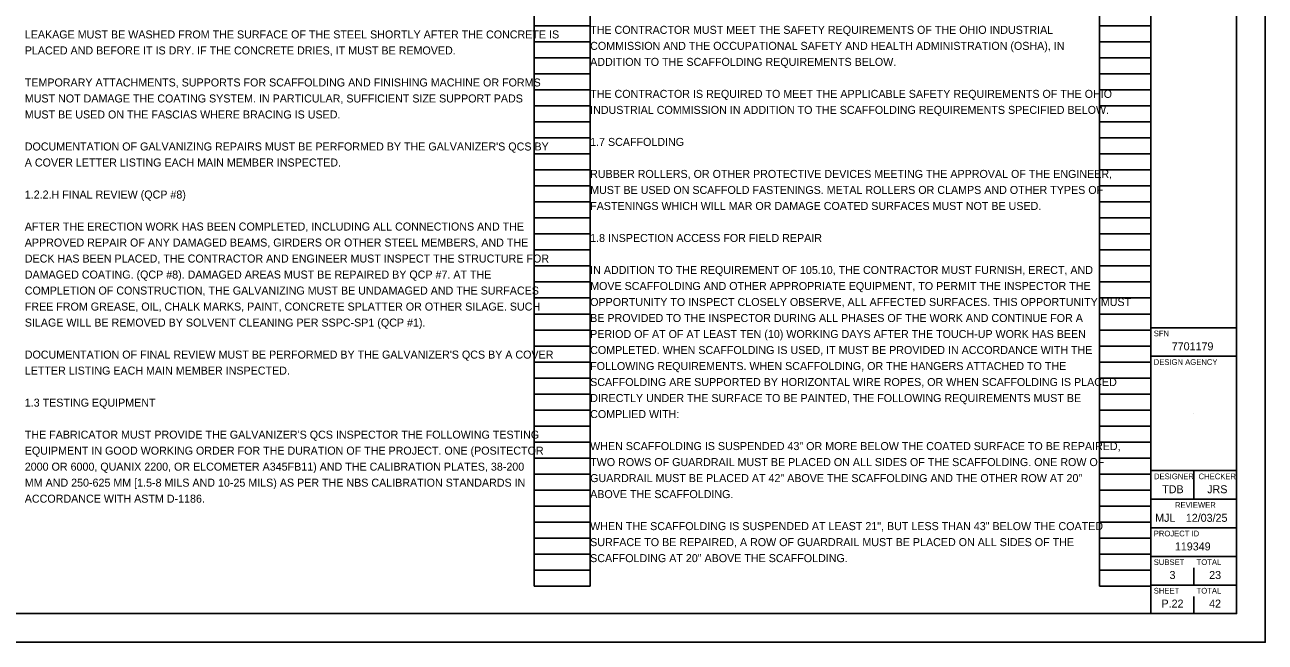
# Model space of a CAD drawing. Extents: x 0 to 34, y 0 to 22.
# Drawn here: x 12.29 to 34, y 0 to 10.8 of the extents above; entities that cross this region are included whole.
import ezdxf

# ---------------------------------------------------------------- set-up
doc = ezdxf.new("R2010")
doc.units = 0
for name, color, linetype in [('SH_Border', 7, 'Continuous'), ('SH_Cut_Line', 7, 'Continuous'), ('SH_Data', 7, 'Continuous'), ('SH_Text', 7, 'Continuous')]:
    doc.layers.add(name, color=color, linetype=linetype)

msp = doc.modelspace()

# ---------------------------------------------------------------- linework, layer by layer
at = {"layer": 'SH_Border'}
for p, q in [((32, 0.5), (32, 21.5)), ((32, 5.5), (33.5, 5.5)), ((32, 5), (33.5, 5)), ((32, 3), (33.5, 3)), ((32.75, 3), (32.75, 2.5)), ((32, 2.5), (33.5, 2.5)), ((32, 2), (33.5, 2)), ((32, 1.5), (33.5, 1.5)), ((32, 1), (33.5, 1))]:
    msp.add_line(p, q, dxfattribs=at)
msp.add_lwpolyline([(1.5, 21.5), (33.5, 21.5), (33.5, 0.5), (1.5, 0.5)], close=True, dxfattribs=at)
at = {"layer": 'SH_Cut_Line'}
msp.add_lwpolyline([(0, 0), (34, 0), (34, 22), (0, 22)], close=True, dxfattribs=at)
at = {"layer": 'SH_Data'}
for p, q in [((21.207, 0.98), (21.207, 21.14)), ((22.187, 0.98), (22.187, 21.14)), ((31.1, 0.98), (31.1, 21.14)), ((32, 0.98), (32, 21.14)), ((21.207, 10.78), (22.187, 10.78)), ((31.1, 10.78), (32, 10.78)), ((21.207, 10.5), (22.187, 10.5)), ((31.1, 10.5), (32, 10.5)), ((21.207, 10.22), (22.187, 10.22)), ((31.1, 10.22), (32, 10.22)), ((21.207, 9.94), (22.187, 9.94)), ((31.1, 9.94), (32, 9.94)), ((21.207, 9.66), (22.187, 9.66)), ((31.1, 9.66), (32, 9.66)), ((21.207, 9.38), (22.187, 9.38)), ((31.1, 9.38), (32, 9.38)), ((21.207, 9.1), (22.187, 9.1)), ((31.1, 9.1), (32, 9.1)), ((21.207, 8.82), (22.187, 8.82)), ((31.1, 8.82), (32, 8.82)), ((21.207, 8.54), (22.187, 8.54)), ((31.1, 8.54), (32, 8.54)), ((21.207, 8.26), (22.187, 8.26)), ((31.1, 8.26), (32, 8.26)), ((21.207, 7.98), (22.187, 7.98)), ((31.1, 7.98), (32, 7.98)), ((21.207, 7.7), (22.187, 7.7)), ((31.1, 7.7), (32, 7.7)), ((21.207, 7.42), (22.187, 7.42)), ((31.1, 7.42), (32, 7.42)), ((21.207, 7.14), (22.187, 7.14)), ((31.1, 7.14), (32, 7.14)), ((21.207, 6.86), (22.187, 6.86)), ((31.1, 6.86), (32, 6.86)), ((21.207, 6.58), (22.187, 6.58)), ((31.1, 6.58), (32, 6.58)), ((21.207, 6.3), (22.187, 6.3)), ((31.1, 6.3), (32, 6.3)), ((21.207, 6.02), (22.187, 6.02)), ((31.1, 6.02), (32, 6.02)), ((21.207, 5.74), (22.187, 5.74)), ((31.1, 5.74), (32, 5.74)), ((21.207, 5.46), (22.187, 5.46)), ((31.1, 5.46), (32, 5.46)), ((21.207, 5.18), (22.187, 5.18)), ((31.1, 5.18), (32, 5.18)), ((21.207, 4.9), (22.187, 4.9)), ((31.1, 4.9), (32, 4.9)), ((21.207, 4.62), (22.187, 4.62)), ((31.1, 4.62), (32, 4.62)), ((21.207, 4.34), (22.187, 4.34)), ((31.1, 4.34), (32, 4.34)), ((21.207, 4.06), (22.187, 4.06)), ((31.1, 4.06), (32, 4.06)), ((32.75, 4), (32.75, 4)), ((21.207, 3.78), (22.187, 3.78)), ((31.1, 3.78), (32, 3.78)), ((21.207, 3.5), (22.187, 3.5)), ((31.1, 3.5), (32, 3.5)), ((21.207, 3.22), (22.187, 3.22)), ((31.1, 3.22), (32, 3.22)), ((21.207, 2.94), (22.187, 2.94)), ((31.1, 2.94), (32, 2.94)), ((21.207, 2.66), (22.187, 2.66)), ((31.1, 2.66), (32, 2.66)), ((21.207, 2.38), (22.187, 2.38)), ((31.1, 2.38), (32, 2.38)), ((21.207, 2.1), (22.187, 2.1)), ((31.1, 2.1), (32, 2.1)), ((21.207, 1.82), (22.187, 1.82)), ((31.1, 1.82), (32, 1.82)), ((21.207, 1.54), (22.187, 1.54)), ((31.1, 1.54), (32, 1.54)), ((21.207, 1.26), (22.187, 1.26)), ((31.1, 1.26), (32, 1.26)), ((32.75, 1), (32.75, 1.3)), ((21.207, 0.98), (22.187, 0.98)), ((31.1, 0.98), (32, 0.98)), ((32.375, 0.675), (32.375, 0.675)), ((32.75, 0.5), (32.75, 0.8))]:
    msp.add_line(p, q, dxfattribs=at)

# ---------------------------------------------------------------- texts
for s, height, p in [('SFN', 0.1, (32.05, 5.35)), ('7701179', 0.14, (32.365, 5.105)), ('DESIGN AGENCY', 0.1, (32.05, 4.85)), ('DESIGNER', 0.1, (32.054, 2.85)), ('CHECKER', 0.1, (32.835, 2.85)), ('TDB', 0.14, (32.198, 2.605)), ('JRS', 0.14, (32.985, 2.605)), ('REVIEWER', 0.1, (32.422, 2.35)), ('MJL', 0.14, (32.075, 2.105)), ('12/03/25', 0.14, (32.611, 2.105)), ('PROJECT ID', 0.1, (32.05, 1.85)), ('119349', 0.14, (32.42, 1.605)), ('SUBSET', 0.1, (32.05, 1.35)), ('TOTAL', 0.1, (32.8, 1.35)), ('3', 0.14, (32.326, 1.105)), ('23', 0.14, (33.02, 1.105)), ('SHEET', 0.1, (32.05, 0.85)), ('TOTAL', 0.1, (32.8, 0.85)), ('P.22', 0.14, (32.185, 0.605)), ('42', 0.14, (33.019, 0.605))]:
    msp.add_text(s, height=height, dxfattribs=at).set_placement(p)
at = {"layer": 'SH_Text'}
for s, p in [('LEAKAGE MUST BE WASHED FROM THE SURFACE OF THE STEEL SHORTLY AFTER THE CONCRETE IS ', (12.293, 10.56)), ('THE CONTRACTOR MUST MEET THE SAFETY REQUIREMENTS OF THE OHIO INDUSTRIAL ', (22.187, 10.64)), ('PLACED AND BEFORE IT IS DRY. IF THE CONCRETE DRIES, IT MUST BE REMOVED.', (12.293, 10.28)), ('COMMISSION AND THE OCCUPATIONAL SAFETY AND HEALTH ADMINISTRATION (OSHA), IN ', (22.187, 10.36)), ('ADDITION TO THE SCAFFOLDING REQUIREMENTS BELOW.', (22.187, 10.08)), ('TEMPORARY ATTACHMENTS, SUPPORTS FOR SCAFFOLDING AND FINISHING MACHINE OR FORMS ', (12.293, 9.72)), ('MUST NOT DAMAGE THE COATING SYSTEM. IN PARTICULAR, SUFFICIENT SIZE SUPPORT PADS ', (12.293, 9.44)), ('THE CONTRACTOR IS REQUIRED TO MEET THE APPLICABLE SAFETY REQUIREMENTS OF THE OHIO ', (22.187, 9.52)), ('INDUSTRIAL COMMISSION IN ADDITION TO THE SCAFFOLDING REQUIREMENTS SPECIFIED BELOW.', (22.187, 9.24)), ('MUST BE USED ON THE FASCIAS WHERE BRACING IS USED.', (12.293, 9.16)), ("DOCUMENTATION OF GALVANIZING REPAIRS MUST BE PERFORMED BY THE GALVANIZER'S QCS BY ", (12.293, 8.6)), ('1.7 SCAFFOLDING', (22.187, 8.68)), ('A COVER LETTER LISTING EACH MAIN MEMBER INSPECTED.', (12.293, 8.32)), ('RUBBER ROLLERS, OR OTHER PROTECTIVE DEVICES MEETING THE APPROVAL OF THE ENGINEER, ', (22.187, 8.12)), ('1.2.2.H FINAL REVIEW (QCP #8)', (12.293, 7.76)), ('MUST BE USED ON SCAFFOLD FASTENINGS. METAL ROLLERS OR CLAMPS AND OTHER TYPES OF ', (22.187, 7.84)), ('FASTENINGS WHICH WILL MAR OR DAMAGE COATED SURFACES MUST NOT BE USED.', (22.187, 7.56)), ('AFTER THE ERECTION WORK HAS BEEN COMPLETED, INCLUDING ALL CONNECTIONS AND THE ', (12.293, 7.2)), ('APPROVED REPAIR OF ANY DAMAGED BEAMS, GIRDERS OR OTHER STEEL MEMBERS, AND THE ', (12.293, 6.92)), ('1.8 INSPECTION ACCESS FOR FIELD REPAIR', (22.187, 7)), ('DECK HAS BEEN PLACED, THE CONTRACTOR AND ENGINEER MUST INSPECT THE STRUCTURE FOR ', (12.293, 6.64)), ('IN ADDITION TO THE REQUIREMENT OF 105.10, THE CONTRACTOR MUST FURNISH, ERECT, AND ', (22.187, 6.44)), ('DAMAGED COATING. (QCP #8). DAMAGED AREAS MUST BE REPAIRED BY QCP #7. AT THE ', (12.293, 6.36)), ('MOVE SCAFFOLDING AND OTHER APPROPRIATE EQUIPMENT, TO PERMIT THE INSPECTOR THE ', (22.187, 6.16)), ('COMPLETION OF CONSTRUCTION, THE GALVANIZING MUST BE UNDAMAGED AND THE SURFACES ', (12.293, 6.08)), ('FREE FROM GREASE, OIL, CHALK MARKS, PAINT, CONCRETE SPLATTER OR OTHER SILAGE. SUCH ', (12.293, 5.8)), ('OPPORTUNITY TO INSPECT CLOSELY OBSERVE, ALL AFFECTED SURFACES. THIS OPPORTUNITY MUST ', (22.187, 5.88)), ('SILAGE WILL BE REMOVED BY SOLVENT CLEANING PER SSPC-SP1 (QCP #1).', (12.293, 5.52)), ('BE PROVIDED TO THE INSPECTOR DURING ALL PHASES OF THE WORK AND CONTINUE FOR A ', (22.187, 5.6)), ('PERIOD OF AT OF AT LEAST TEN (10) WORKING DAYS AFTER THE TOUCH-UP WORK HAS BEEN ', (22.187, 5.32)), ("DOCUMENTATION OF FINAL REVIEW MUST BE PERFORMED BY THE GALVANIZER'S QCS BY A COVER ", (12.293, 4.96)), ('COMPLETED. WHEN SCAFFOLDING IS USED, IT MUST BE PROVIDED IN ACCORDANCE WITH THE ', (22.187, 5.04)), ('LETTER LISTING EACH MAIN MEMBER INSPECTED.', (12.293, 4.68)), ('FOLLOWING REQUIREMENTS. WHEN SCAFFOLDING, OR THE HANGERS ATTACHED TO THE ', (22.187, 4.76)), ('SCAFFOLDING ARE SUPPORTED BY HORIZONTAL WIRE ROPES, OR WHEN SCAFFOLDING IS PLACED ', (22.187, 4.48)), ('DIRECTLY UNDER THE SURFACE TO BE PAINTED, THE FOLLOWING REQUIREMENTS MUST BE ', (22.187, 4.2)), ('1.3 TESTING EQUIPMENT', (12.293, 4.12)), ('COMPLIED WITH:', (22.187, 3.92)), ("THE FABRICATOR MUST PROVIDE THE GALVANIZER'S QCS INSPECTOR THE FOLLOWING TESTING ", (12.293, 3.56)), ('WHEN SCAFFOLDING IS SUSPENDED 43" OR MORE BELOW THE COATED SURFACE TO BE REPAIRED, ', (22.187, 3.36)), ('EQUIPMENT IN GOOD WORKING ORDER FOR THE DURATION OF THE PROJECT. ONE (POSITECTOR ', (12.293, 3.28)), ('2000 OR 6000, QUANIX 2200, OR ELCOMETER A345FB11) AND THE CALIBRATION PLATES, 38-200 ', (12.293, 3)), ('TWO ROWS OF GUARDRAIL MUST BE PLACED ON ALL SIDES OF THE SCAFFOLDING. ONE ROW OF ', (22.187, 3.08)), ('MM AND 250-625 MM [1.5-8 MILS AND 10-25 MILS) AS PER THE NBS CALIBRATION STANDARDS IN ', (12.293, 2.72)), ('GUARDRAIL MUST BE PLACED AT 42" ABOVE THE SCAFFOLDING AND THE OTHER ROW AT 20" ', (22.187, 2.8)), ('ABOVE THE SCAFFOLDING.', (22.187, 2.52)), ('ACCORDANCE WITH ASTM D-1186.', (12.293, 2.44)), ('WHEN THE SCAFFOLDING IS SUSPENDED AT LEAST 21", BUT LESS THAN 43" BELOW THE COATED ', (22.187, 1.96)), ('SURFACE TO BE REPAIRED, A ROW OF GUARDRAIL MUST BE PLACED ON ALL SIDES OF THE ', (22.187, 1.68)), ('SCAFFOLDING AT 20" ABOVE THE SCAFFOLDING.', (22.187, 1.4))]:
    msp.add_text(s, height=0.14, dxfattribs=at).set_placement(p)

doc.saveas('drawing.dxf')
